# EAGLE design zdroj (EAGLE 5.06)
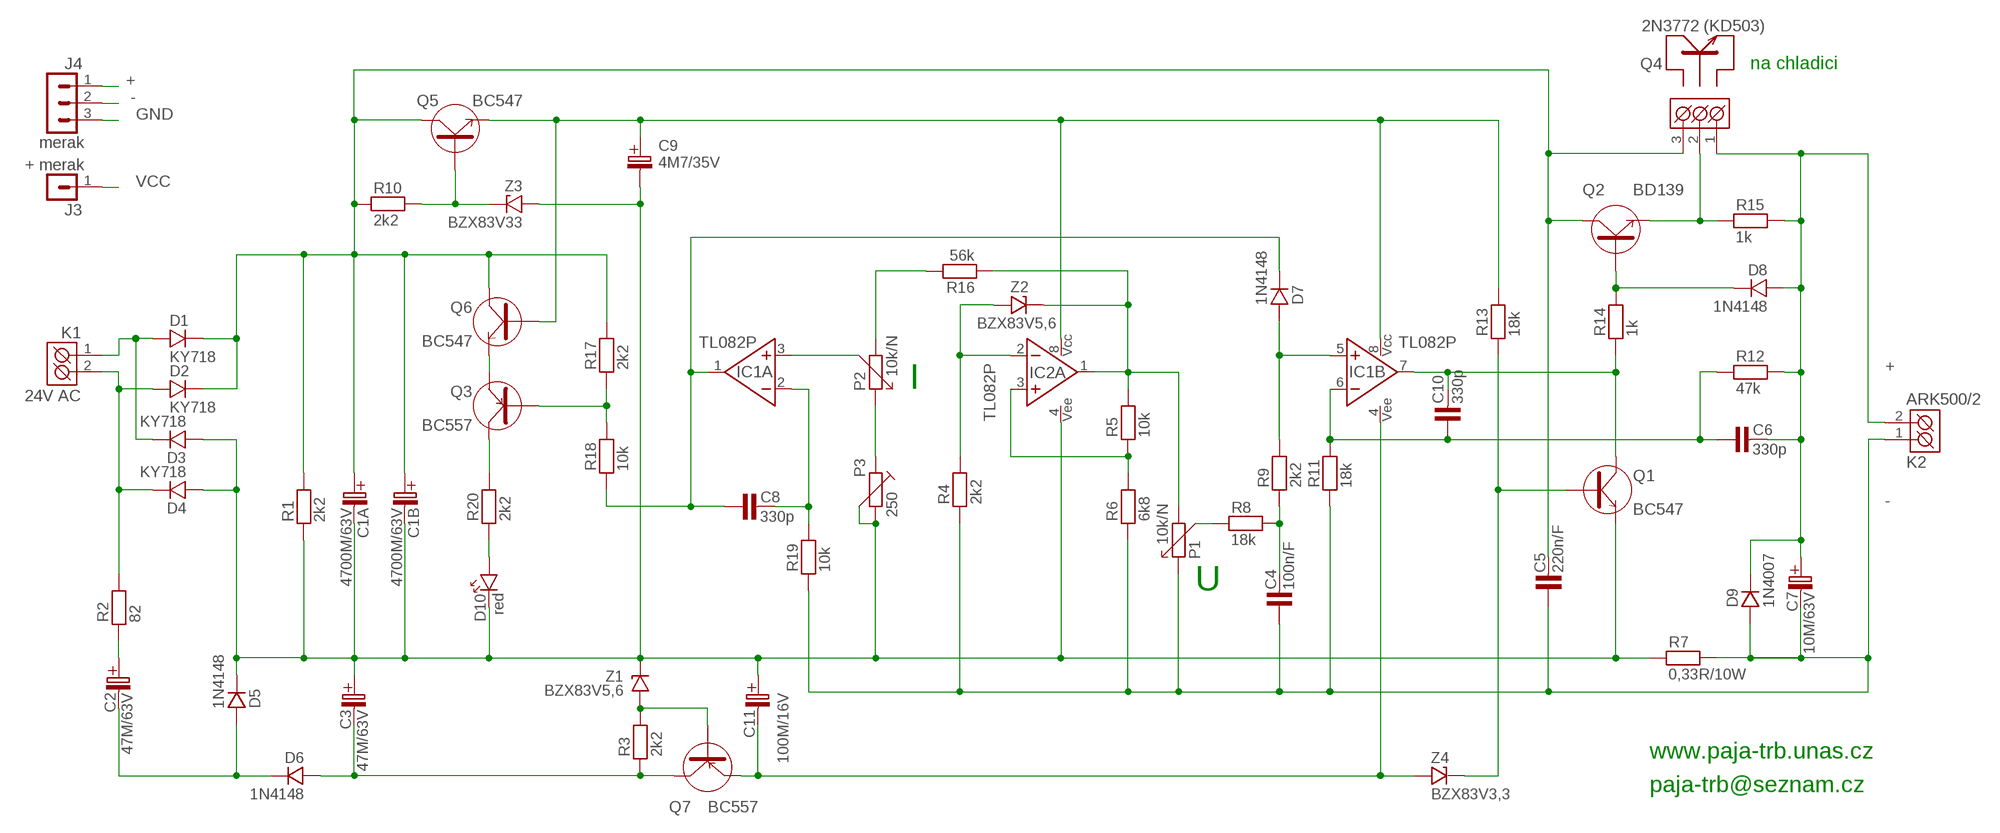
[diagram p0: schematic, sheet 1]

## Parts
C1A  4700M/63V  [C_EL12,5]
C1B  4700M/63V  [C_EL12,5]
C2  47M/63V  [C_EL_3,5]
C3  47M/63V  [C_EL_3,5]
C4  100n/F  100N-K/100  [RM5_3,2]
C5  220n/F  220N-K/63V  [RM5_3,2]
C6  330p  C-KERAMIK_SMD_1206  [1206]
C7  10M/63V  [C_EL_2]
C8  330p  C-KERAMIK_SMD_1206  [1206]
C9  4M7/35V  4M7/50V  [C_EL_2]
C10  330p  C-KERAMIK_SMD_1206  [1206]
C11  100M/16V  [C_EL_2,5]
D1  KY718  D_KY718  [D_KY718]
D2  KY718  D_KY718  [D_KY718]
D3  KY718  D_KY718  [D_KY718]
D4  KY718  D_KY718  [D_KY718]
D5  1N4148  1N4148_7,5  [DO35]
D6  1N4148  1N4148_7,5  [DO35]
D7  1N4148  1N4148_7,5  [DO35]
D8  1N4148  1N4148_7,5  [DO35]
D9  1N4007  1N4007_10  [DO41]
D10  red  LED_5  [LED_5]
IC1  TL082P  TL072  [DIL8]
IC2  TL082P  TL072  [DIL8]
J3  + merak  S1G1_JUMP  [S1G1_JUM]
J4  merak  S1G3_JUMP  [S1G3_JUM]
K1  24V AC  ARK500/2  [ARK500/2]
K2  ARK500/2  [ARK500/2]
P1  10k/N  PC16ML"  [PC16ML]
P2  10k/N  PC16ML"  [PC16ML]
P3  250  TRIMRPT10V  [PT10V]
Q1  BC547  BC546  [TO-92]
Q2  BD139  BD139_STOJ  [TO-126S]
Q3  BC557  BC556  [TO-92]
Q4  2N3772 (KD503)  ARK500/3  [ARK500/3]
Q5  BC547  BC546  [TO-92]
Q6  BC547  BC546  [TO-92]
Q7  BC557  BC556  [TO-92]
R1  2k2  W2_2K2  [R__2W]
R2  82  R_7,5  [R-7,5]
R3  2k2  R_7,5  [R-7,5]
R4  2k2  R_SMD_1206  [1206]
R5  10k  R_SMD_1206  [1206]
R6  6k8  R_SMD_1206  [1206]
R7  0,33R/10W  R__10W  [R-_10W]
R8  18k  R_10  [R-10]
R9  2k2  R_7,5  [R-7,5]
R10  2k2  R_7,5  [R-7,5]
R11  18k  R_7,5  [R-7,5]
R12  47k  R_7,5  [R-7,5]
R13  18k  R_10  [R-10]
R14  1k  R_7,5  [R-7,5]
R15  1k  R_7,5  [R-7,5]
R16  56k  R_SMD_1206  [1206]
R17  2k2  R_7,5  [R-7,5]
R18  10k  R_7,5  [R-7,5]
R19  10k  R_10  [R-10]
R20  2k2  R_SMD_1206  [1206]
Z1  BZX83V5,6  D-ZENEROVA_0,5W_BZX83V  [DO35]
Z2  BZX83V5,6  D-ZENEROVA_0,5W_BZX83V  [DO35]
Z3  BZX83V33  D-ZENEROVA_0,5W_BZX83V  [DO35]
Z4  BZX83V3,3  D-ZENEROVA_2W_BZY  [DO41]

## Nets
+: C6.2 C7.C+(C_EL+) D8.A D9.K J4.1 K2.2(K2) Q4.1(K1) R12.2 R15.2
-: C4.1 C5.1 C7.C-(C_EL-) D9.A J4.2 K2.1(K1) P1.1 R4.1 R6.1 R7.2 R11.1 R19.1
GND: C1A.C-(C_EL-) C1B.C-(C_EL-) C3.C+(C_EL+) C9.C-(C_EL-) C11.C+(C_EL+) D3.A D4.A D5.K D10.K IC2.4(NS:VEE) J4.3 P3.2 P3.3 Q1.3(E) R1.1 R7.1 Z1.K Z3.A
N$2: Q3.1(C) R20.2
N$3: C2.C+(C_EL+) R2.1
N$5: C2.C-(C_EL-) D5.A D6.K
N$6: C3.C-(C_EL-) D6.A Q7.1(C) R3.1
N$8: C11.C-(C_EL-) IC1.4(NS:VEE) Q7.3(E) Z4.A
N$9: C8.1 D7.K IC1.1(A:VYSTUP) R18.1
N$10: IC1.3(A:NEIN+) P2.3
N$11: Q5.2(B) R10.2 Z3.K
N$12: D10.A R20.1
N$13: Q3.3(E) Q6.3(E)
N$14: P1.3 R8.1
N$15: Q3.2(B) R17.1 R18.2
N$17: C9.C+(C_EL+) IC1.8(NS:VCC) IC2.8(NS:VCC) Q5.3(E) Q6.2(B) R13.2
N$18: C8.2 IC1.2(A:IN-) R19.2
N$19: P2.1 P3.1
N$22: IC2.2(A:IN-) R4.2 Z2.A
N$23: IC2.3(A:NEIN+) R5.1 R6.2
N$24: IC2.1(A:VYSTUP) P1.2 R5.2 R16.1 Z2.K
N$25: P2.2 R16.2
N$27: C4.2 R8.2 R9.1
N$28: D7.A IC1.5(B:NEIN+) R9.2
N$29: C6.1 C10.1 IC1.6(B:IN-) R11.2 R12.1
N$31: C10.2 IC1.7(B:VYSTUP) Q1.1(C) R14.1
N$32: Q1.2(B) R13.1 Z4.K
N$33: Q2.1(E) Q4.2(K2) R15.1
N$36: D8.K Q2.3(B) R14.2
STRID1: D1.A D3.K K1.1(K1)
STRID2: D2.A D4.K K1.2(K2) R2.2
VCC: C1A.C+(C_EL+) C1B.C+(C_EL+) C5.2 D1.K D2.K J3.1 Q2.2(C) Q4.3(K3) Q5.1(C) Q6.1(C) R1.2 R10.1 R17.2
Z1: Q7.2(B) R3.2 Z1.A
Unconnected: IC2.5(B:NEIN+) IC2.6(B:IN-) IC2.7(B:VYSTUP)

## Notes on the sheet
- na chladici
- I
- U
- www.paja-trb.unas.cz
- paja-trb@seznam.cz

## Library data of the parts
C1A C1B = #PaJa_C-el_2:4700M/63V
C2 C3 = #PaJa_C-el_2:47M/63V
C4 = #PaJa_C-folie:100N-K/100
C5 = #PaJa_C-folie:220N-K/63V
C6 C8 C10 = #PaJa_23_e56:C-KERAMIK: Kondenzator - keramicky
C7 = #PaJa_C-el_2:10M/63V
C9 = #PaJa_C-el_2:4M7/50V
C11 = #PaJa_C-el_2:100M/16V
D1-D4 = #PaJa_23_e56:D: Dioda - univerzální
D5-D8 = #PaJa_23_e56:1N4148: Univerzalni dioda - 0,15A, 75V
D9 = #PaJa_23_e56:1N4007: Usmernovaci dioda - 1A, 1000V
D10 = #PaJa_23_e56:LED: LED - jednobarevna
IC1 IC2 = #PaJa_23_e56:TL072: OZ - JFET - 2x
J3 = #PaJa_23_e56:S1G1_JUMP: Radove konektory - koliky - 1x
J4 = #PaJa_23_e56:S1G3_JUMP: Radove konektory - koliky - 3x
K1 K2 = #PaJa_23_e56:ARK500/2: Svorkovnice - roztec 5mm - dvojita
P1 P2 = #PaJa_23_e56:PC16ML: Potenciometr - plastovy - mono - 100R az 5M
P3 = #PaJa_23_e56:TRIMR: Trimr
Q1 Q5 Q6 = #PaJa_23_e56:BC546: Tranzistor NPN - Univerzalni NF - Ic=0,1A
Q2 = #PaJa_23_e56:BD139: Tranzistor NPN - Vykonovy - Ic=1,5A
Q3 Q7 = #PaJa_23_e56:BC556: Tranzistor PNP - Univerzalni NF - Ic=0,1A
Q4 = #PaJa_23_e56:ARK500/3: Svorkovnice - roztec 5mm - trojita
R1 = #PaJa_R:W2_2K2
R2-R20 = #PaJa_23_e56:R: Rezistor
Z1-Z4 = #PaJa_23_e56:D-ZENEROVA: Zenerova dioda

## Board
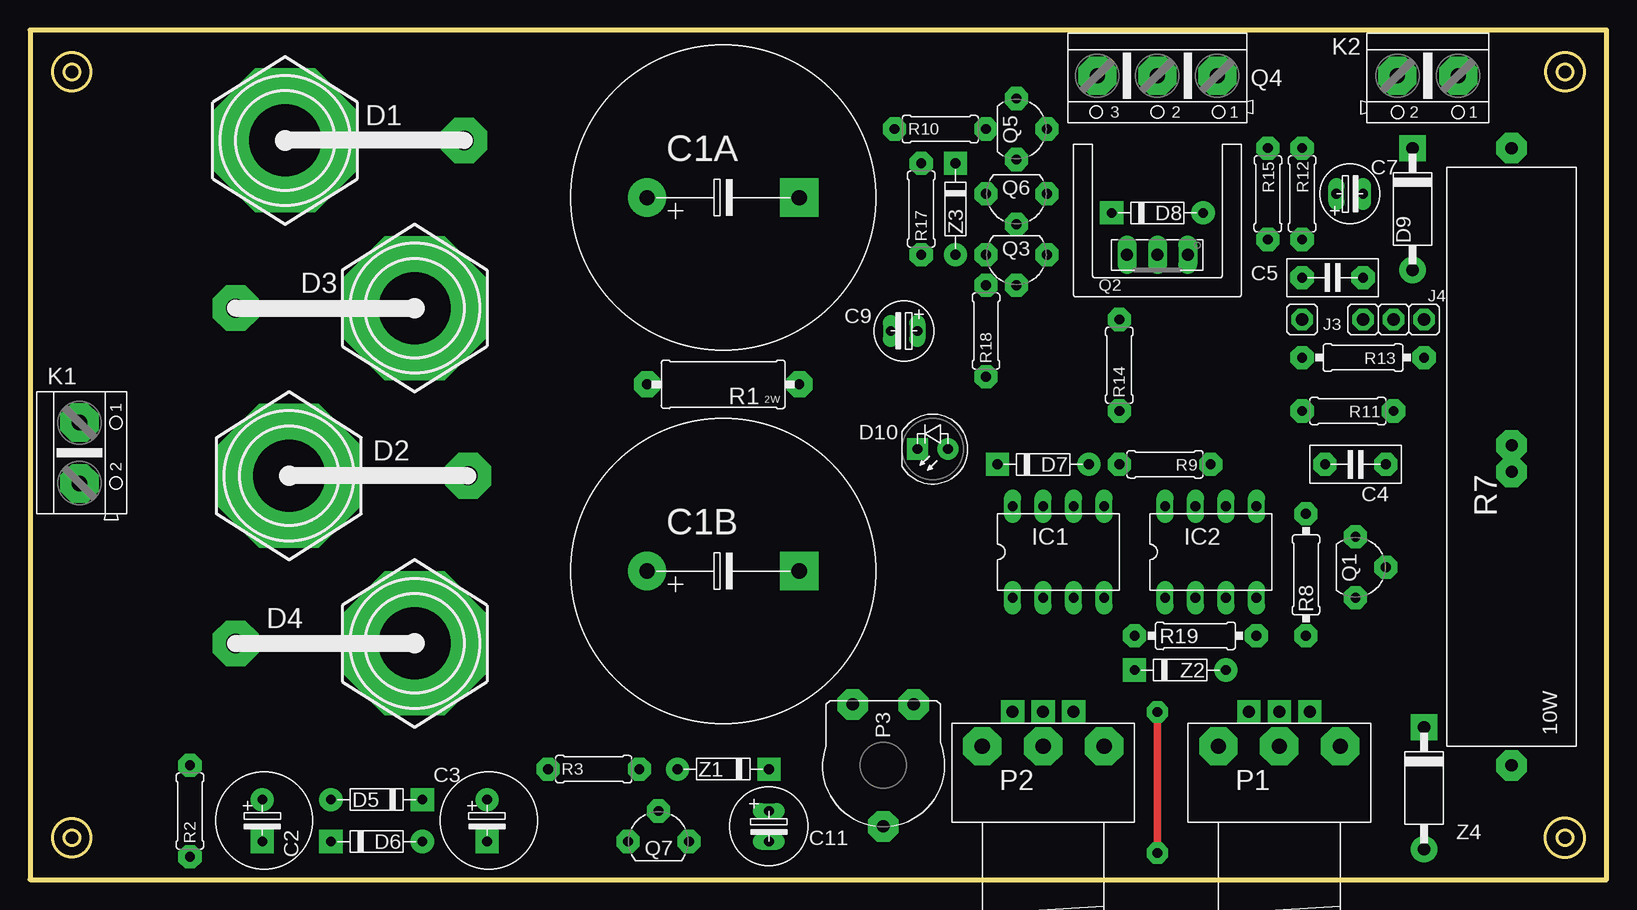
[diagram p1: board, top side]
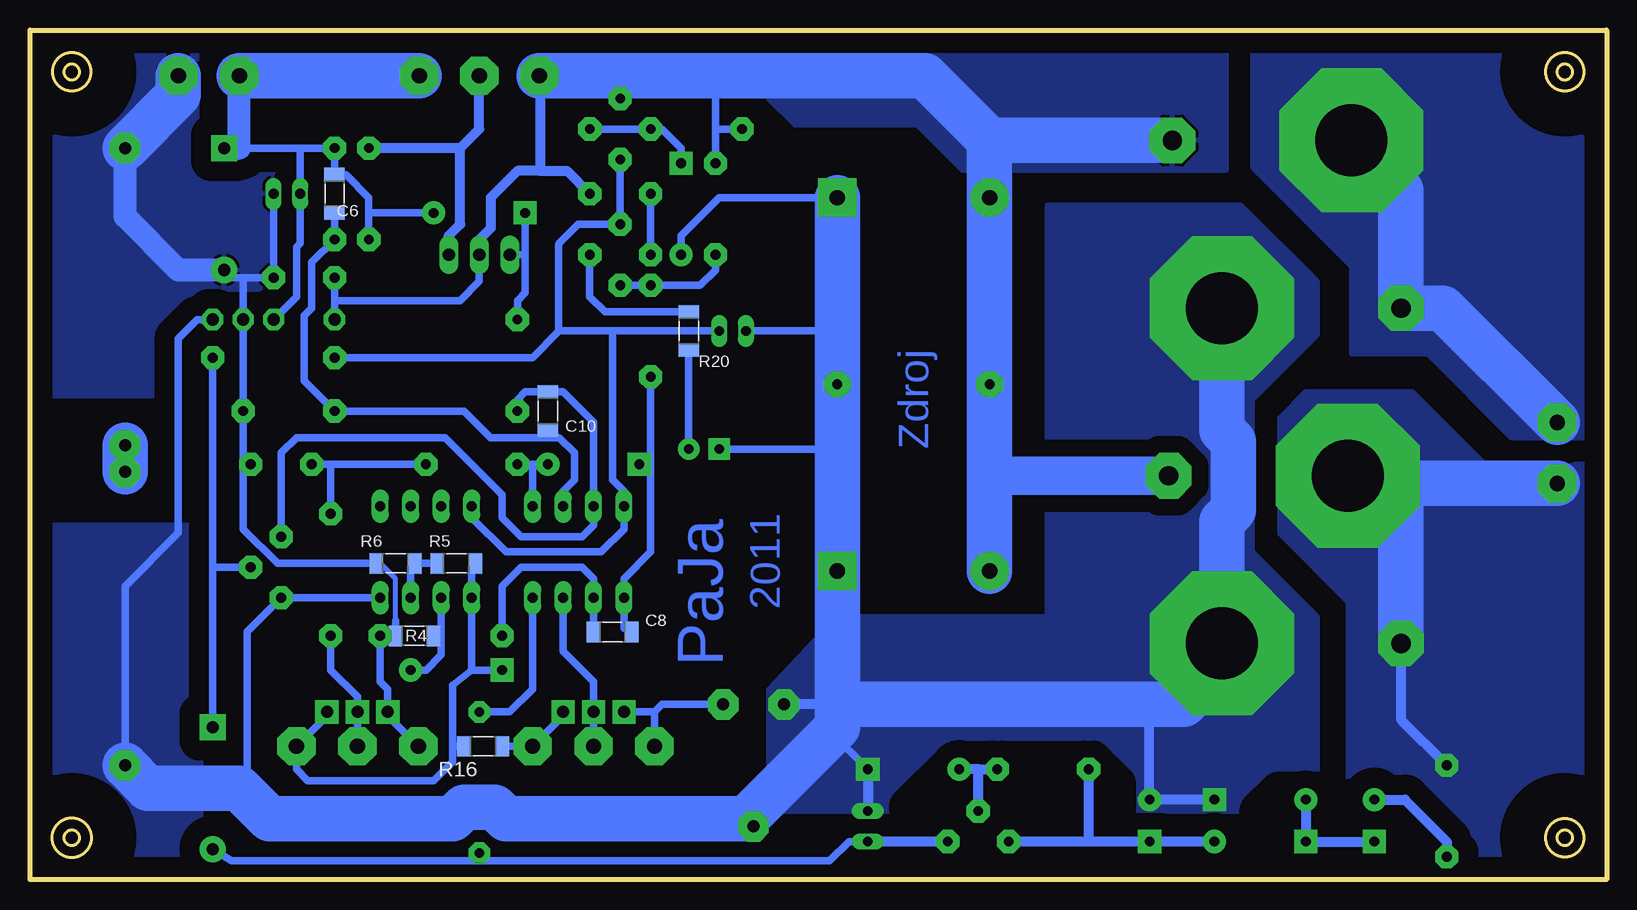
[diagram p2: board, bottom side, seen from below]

Size 131.43 x 70.79 mm. Coordinates in mm from the lower left corner, seen from the top.
Outline: 0,0 131.43,0 131.43,70.79 0,70.79 0,0
Outline: circle at 127.95,67.31 radius 1.59
Outline: circle at 127.95,67.31 radius 0.64
Outline: circle at 127.95,3.49 radius 0.64
Outline: circle at 127.95,3.49 radius 1.62
Outline: circle at 3.49,3.49 radius 0.64
Outline: circle at 3.49,3.49 radius 1.59
Outline: circle at 3.49,67.31 radius 0.64
Outline: circle at 3.49,67.31 radius 1.59
Copper layers (1*16): Top 0.035mm / dielectric 1.5mm / Bottom 0.035mm
Design rules "default": minimum track width 10mil, minimum drill 24mil, track to track 8mil, track to pad 8mil, pad to pad 8mil, via to via 8mil, smd to smd 8mil, copper to edge 40mil, drill to drill 8mil, minimum pad ring 10mil, minimum via ring 8mil, stop-mask expansion 4mil, vias tented up to drill 0mil, thermal gap 10mil
Holes 3.2 mm at 3.49,3.49 3.49,67.31 127.95,67.31 127.95,3.49
bRestrict: area 0,63.8 to 7,70.8; area 0,0 to 7,7; area 124.5,63.8 to 131.4,70.8; area 124.5,0 to 131.4,7; 8 lines

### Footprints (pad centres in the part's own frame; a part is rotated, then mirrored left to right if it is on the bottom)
C_EL12,5 = drill 1.27 pad 3.2 round: C+ -6.35,0 | drill 1.27 pad 3.2 square: C- 6.35,0
C_EL_3,5 = drill 0.813 pad 1.93 round: C+ 0,0 | drill 0.813 pad 1.93 square: C- 3.493,0
RM5_3,2 = drill 0.813 pad 1.93 octagon: 1 -2.54,0; 2 2.54,0
1206 = smd 1.143 x 1.702: 1 -1.587,0; 2 1.587,0
C_EL_2 = drill 0.813 pad 1.27 long: C+ 0,0; C- 2.223,0
C_EL_2,5 = drill 0.813 pad 1.27 long: C+ -1.27,0; C- 1.27,0
D_KY718 = drill 6 pad 12 octagon: A 0,0 | drill 1.6 pad 3.81 octagon: K 14.922,0
DO35 = drill 0.813 pad 1.93 round: A -3.81,0 | drill 0.813 pad 1.93 square: K 3.81,0
DO41 = drill 1.016 pad 2.184 round: A -5.08,0 | drill 1.016 pad 2.184 square: K 5.08,0
LED_5 = drill 0.813 pad 1.778 round: A -1.27,0 | drill 0.813 pad 1.778 square: K 1.27,0
DIL8 = drill 0.813 pad 1.4 long: 1 -3.81,-3.81; 2 -1.27,-3.81; 3 1.27,-3.81; 4 3.81,-3.81; 5 3.81,3.81; 6 1.27,3.81; 7 -1.27,3.81; 8 -3.81,3.81
S1G1_JUM = drill 1.016 pad 1.778 octagon: 1 0,0
S1G3_JUM = drill 1.016 pad 1.778 octagon: 1 -2.54,0; 2 0,0; 3 2.54,0
ARK500/2 = drill 1.27 pad 3.2 octagon: 1 -2.54,0; 2 2.54,0
PC16ML = drill 1.27 pad 3.2 octagon: 1 -5.08,0; 2 5.08,0; 3 0,0
PT10V = drill 1.016 pad 2.54 octagon: 1 -2.54,-5.08; 2 0,5.08; 3 2.54,-5.08
TO-92 = drill 0.813 pad 1.93 octagon: 1 0,2.54; 2 2.54,0; 3 0,-2.54
TO-126S = drill 1.016 pad 1.6 long: 1 -2.54,0; 2 0,0; 3 2.54,0
ARK500/3 = drill 1.27 pad 3.2 octagon: 1 -5,0; 2 0,0; 3 5,0
R__2W = drill 0.813 pad 2.184 octagon: 1 -6.35,0; 2 6.35,0
R-7,5 = drill 0.813 pad 1.93 octagon: 1 -3.81,0; 2 3.81,0
R-_10W = drill 1.016 pad 2.54 octagon: 1 -25.718,0; 2 25.718,0
R-10 = drill 0.813 pad 1.93 octagon: 1 -5.08,0; 2 5.08,0

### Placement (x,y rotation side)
C1A  57.78,56.83 0 top
C1B  57.78,25.72 0 top
C2  19.37,6.67 270 top
C3  38.1,6.67 270 top
C4  110.49,34.61 180 top
C5  108.58,50.16 180 top
C6  106.05,57.15 90 bottom
C7  108.9,57.15 0 top
C8  82.87,20.64 180 bottom
C9  73.98,45.72 180 top
C10  88.27,39.05 90 bottom
C11  61.59,4.45 270 top
CHLAD  [CH_DO1_S]  93.98,48.58 180 top
D1  21.27,61.59 0 top
D2  21.59,33.66 0 top
D3  32.07,47.62 180 top
D4  32.07,19.68 180 top
D5  28.89,6.67 0 top
D6  28.89,3.17 180 top
D7  84.45,34.61 180 top
D8  93.98,55.56 180 top
D9  115.25,55.88 90 top
D10  75.25,35.88 180 top
IC1  85.72,27.3 0 top
IC2  98.42,27.3 0 top
J3  106.05,46.67 0 top
J4  113.67,46.67 0 top
K1  4.13,35.56 270 top
K2  116.52,66.99 180 top
P1  104.14,11.11 0 top
P2  84.45,11.11 0 top
P3  71.12,9.53 180 top
Q1  110.49,26.04 0 top
Q2  93.98,52.07 180 top
Q3  82.23,52.07 270 top
Q4  93.98,66.99 180 top
Q5  82.23,62.55 0 top
Q6  82.23,57.15 270 top
Q7  52.39,3.17 90 top
R1  57.78,41.27 180 top
R2  13.34,5.71 90 top
R3  46.99,9.21 0 top
R4  99.38,20.32 0 bottom
R5  95.88,26.35 0 bottom
R6  100.97,26.35 0 bottom
R7  123.51,35.24 90 top
R8  106.36,25.4 90 top
R9  94.62,34.61 180 top
R10  75.88,62.55 0 top
R11  109.86,39.05 180 top
R12  106.05,57.15 90 top
R13  111.12,43.5 180 top
R14  90.81,42.86 90 top
R15  103.19,57.15 270 top
R16  93.66,11.11 0 bottom
R17  74.3,55.88 90 top
R18  79.69,45.72 90 top
R19  97.16,20.32 180 top
R20  76.52,45.72 90 bottom
Z1  57.78,9.21 0 top
Z2  95.88,17.46 180 top
Z3  77.15,55.88 90 top
Z4  116.2,7.62 90 top

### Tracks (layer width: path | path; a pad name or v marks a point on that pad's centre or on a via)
+
  Bottom 0.61: 108.9,60.96 R12.2 C6.2 105.09,58.74 103.19,56.83 103.19,55.56 | 108.9,60.96 D9.K | D8.A 103.19,55.56 | 103.19,55.56 R15.2 | 108.9,60.96 C7.C+ 108.9,53.02 109.22,52.7 109.22,48.58 J4.1
  Bottom 1.93: K2.2 113.98,60.96 D9.K
  Bottom 3.81: K2.2 Q4.1
-  (via drill 1 pad 1.93)
  Bottom 0.406: 100.97,21.59 100.97,25.08 102.23,26.35 R6.1
  Bottom 0.61: R6.1 110.81,26.35 113.67,29.21 113.67,34.61 | 100.97,21.59 R4.1 R19.1 102.23,16.51 101.6,15.88 v101.6,13.97 101.6,13.65 P1.1 | 113.67,50.16 C5.1 C7.C- | 113.67,50.16 115.25,50.16 D9.A | 113.67,50.16 J4.2 R11.1 113.67,36.83 113.67,34.61 | 113.67,34.61 C4.1
  Bottom 1.93: R7.2 123.51,55.24 119.06,50.8 D9.A
  Bottom 3.81: K2.1 119.06,65.41 R7.2
  pour Bottom (isolate 1.676): 131.44,70.8 131.44,40.32 117.16,40.32 117.16,49.21 110.49,49.21 110.49,58.74 117.47,58.74 117.47,70.8
A  (via drill 1 pad 2.54)
  Bottom 3.81: v123.51,33.97 v123.51,36.2
GND
  Bottom 0.61: IC2.4 Q1.3 113.35,20.64 113.35,8.26 113.98,7.62 | 64.14,45.72 C9.C- | 64.14,35.88 D10.K | C1A.C- 73.98,56.83 77.15,53.66 Z3.A | 64.77,12.38 Z1.K | 71.76,5.08 P3.2 | R7.1 123.51,24.45 119.06,28.89 119.06,45.09 117.47,46.67 J4.3
  Bottom 0.813: D5.K C3.C+ 38.1,14.61 | Z1.K C11.C+ | 64.14,14.61 P3.3 | 64.77,12.38 64.45,12.7 64.14,12.7
  Bottom 3.2: 32.07,17.78 D4.A
  Bottom 3.81: 64.14,14.61 C1B.C- 64.14,35.88 R1.1 64.14,45.72 C1A.C- | D3.A 32.07,37.47 31.12,36.51 31.12,30.8 32.07,29.84 D4.A | 64.14,14.61 38.1,14.61 35.24,14.61 32.07,17.78 | 64.14,14.61 64.14,12.7 71.76,5.08 91.76,5.08 92.71,6.03 95.25,6.03 96.2,5.08 111.44,5.08 113.98,7.62 121.6,7.62 R7.1
  pour Bottom (isolate 1.422, no thermals): 24.13,5.71 24.13,21.91 29.53,27.3 29.53,40.01 24.13,45.4 24.13,49.85 30.48,56.2 46.67,56.2 46.67,21.91 64.14,21.91 64.77,21.27 69.85,15.88 69.85,5.71
  pour Bottom (isolate 1.676): 131.44,0 117.16,0 117.16,29.53 131.44,29.53
N$2
  Bottom 0.61: R20.2 83.5,47.31 84.77,48.58 Q3.1
N$3
  Bottom 0.813: R2.1 13.34,3.17 16.83,6.67 C2.C+
N$5
  Bottom 0.813: D5.A D6.K C2.C-
N$6
  Bottom 0.813: 43.18,3.17 Q7.1 | D6.A C3.C- 43.18,3.17 | 43.18,3.17 R3.1
N$8  (via drill 0.81 pad 1.78)
  Top 0.61: v93.98,2.22 v93.98,13.97
  Bottom 0.406: 93.98,1.59 v93.98,2.22
  Bottom 0.61: C11.C- 63.18,3.17 64.77,1.59 93.98,1.59 114.62,1.59 Z4.A | IC1.4 89.54,15.88 91.44,13.97 v93.98,13.97
  Bottom 0.813: Q7.3 C11.C-
N$9
  Bottom 0.61: C8.1 81.91,20.95 IC1.1 81.91,25.08 79.69,27.3 79.69,34.61 | 79.69,34.61 R18.1 | 79.69,34.61 D7.K
N$10  (via drill 1 pad 1.93)
  Bottom 0.61: IC1.3 86.99,19.05 84.45,16.51 v84.45,13.97 P2.3
N$11
  Bottom 0.61: R10.2 79.37,62.55 | R10.2 Q5.2 | Z3.K 77.15,60.96 78.74,62.55 R10.2
N$12
  Bottom 0.61: D10.A R20.1
N$13
  Bottom 0.61: Q3.3 Q6.3
N$14  (via drill 1 pad 1.93)
  Bottom 0.61: R8.1 106.36,17.46 104.14,15.24 v104.14,13.97 P1.3
N$15
  Bottom 0.61: Q3.2 R18.2 75.56,49.53 74.3,50.8 R17.1
N$17
  Bottom 0.61: IC2.8 94.62,30.16 91.76,27.3 83.82,27.3 81.91,29.21 IC1.8 81.91,32.38 82.87,33.34 82.87,45.72 | Q5.3 Q6.2 85.73,54.61 87.31,53.02 87.38,52.88 87.38,45.72 87.31,45.72 | 82.87,45.72 C9.C+ | 82.87,45.72 87.31,45.72 | 87.31,45.72 89.54,43.5 R13.2
N$18
  Bottom 0.61: R19.2 92.08,24.45 90.49,26.04 85.41,26.04 84.45,25.08 IC1.2 C8.2
N$19  (via drill 1 pad 1.93)
  Bottom 0.61: P3.1 78.74,14.61 79.37,13.97 | 79.37,13.97 P2.1 | 79.37,13.97 v81.91,13.97
N$22
  Bottom 0.61: 97.16,20.32 IC2.2 | 97.16,20.32 R4.2 | 97.16,20.32 97.16,18.73 98.42,17.46 Z2.A
N$23
  Bottom 0.61: IC2.3 99.7,26.04 R6.2 R5.1
N$24  (via drill 1 pad 1.93)
  Bottom 0.61: R5.2 94.62,26.04 IC2.1 94.62,17.46 | 94.62,17.46 Z2.K | 96.2,11.11 96.2,9.84 97.79,8.26 108.27,8.26 109.22,9.21 P1.2 106.68,13.65 v106.68,13.97 | 96.2,11.11 96.2,16.19 94.62,17.46 | R16.1 96.2,11.11
N$25  (via drill 1 pad 1.93)
  Bottom 0.61: R16.2 P2.2 86.99,13.65 v86.99,13.97
N$27
  Bottom 0.61: R9.1 106.36,34.61 | 106.36,34.61 C4.2 | 106.36,34.61 R8.2
N$28
  Bottom 0.61: D7.A 89.22,34.61 | 89.22,34.61 R9.2 | IC1.5 89.54,34.29 89.22,34.61
N$29
  Bottom 0.61: IC1.6 86.99,32.38 86.04,33.34 86.04,35.56 87.31,36.83 88.26,36.83 | R12.1 C6.1 R12.1 | R12.1 107.95,51.44 107.95,47.62 108.58,46.99 108.58,41.59 R11.2 95.25,39.05 93.03,36.83 88.26,36.83 | 88.26,36.83 C10.1
N$31
  Bottom 0.61: Q1.1 110.49,35.56 109.22,36.83 96.84,36.83 92.08,32.07 92.08,30.16 90.49,28.57 85.41,28.57 84.45,29.53 IC1.7 84.45,38.1 86.99,40.64 C10.2 90.17,40.64 90.8,40.01 R14.1
N$32
  Bottom 0.61: Z4.K 116.2,26.04 | 116.2,26.04 R13.1 | 116.2,26.04 Q1.2
N$33
  Bottom 0.813: Q4.2 93.98,62.55 95.57,60.96 | 95.57,60.96 R15.1 | Q2.1 96.52,53.66 95.57,54.61 95.57,60.96
N$36
  Bottom 0.61: 90.17,52.07 Q2.3 | 90.17,52.07 D8.K | 90.17,52.07 90.17,48.9 90.8,48.26 R14.2
STRID1
  Bottom 3.81: K1.1 13.65,47.62 D3.K 17.15,57.47 D1.A
  pour Bottom (isolate 1.676, no thermals): 0,70.8 29.53,70.8 29.53,59.37 21.27,51.12 21.27,43.81 14.92,43.81 7.94,36.83 0,36.83
STRID2
  Bottom 0.813: 17.15,18.41 D4.K 17.15,13.34 R2.2
  Bottom 3.81: D4.K 17.15,33.02 | 17.15,33.02 K1.2 | D2.A 17.78,33.66 arc90 17.15,33.02
  pour Bottom (isolate 1.676, no thermals): 0,34.61 10.16,34.61 16.19,40.64 25.08,40.64 27.3,38.42 27.3,28.89 21.59,23.18 21.59,8.57 16.51,8.57 16.51,0 0,0
VCC
  Bottom 0.406: Q4.3 88.9,66.91
  Bottom 0.61: Q2.2 93.98,49.85 95.57,48.26 106.05,48.26 | 82.23,66.99 Q5.1 | 106.05,48.26 C5.2 | 74.3,66.99 74.3,62.55 | 74.3,62.55 R17.2 | 74.3,62.55 R10.1 | 106.05,48.26 J3.1
  Bottom 0.813: Q2.2 93.98,53.34 93.03,54.29 93.03,56.83 90.8,59.05 88.9,59.05 | Q6.1 86.68,59.05 88.9,59.05 | 88.9,66.91 88.9,59.05
  Bottom 3.2: D2.K 51.44,33.66
  Bottom 3.81: Q4.3 82.23,66.99 74.3,66.99 56.83,66.99 51.44,61.59 | C1B.C+ 51.44,33.66 R1.2 C1A.C+ 51.44,61.59 | 51.44,61.59 D1.K
  pour Bottom (isolate 1.676): 31.75,70.8 31.75,59.05 53.66,59.05 57.47,62.87 67.63,62.87 69.85,65.09 69.85,70.8
Z1
  Bottom 0.813: 52.39,9.21 R3.2 | 52.39,9.21 Z1.A | Q7.2 52.39,9.21

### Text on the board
Bottom: Zdroj | 2011 | PaJa
Zapojeni: Chladice, Al - vingl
